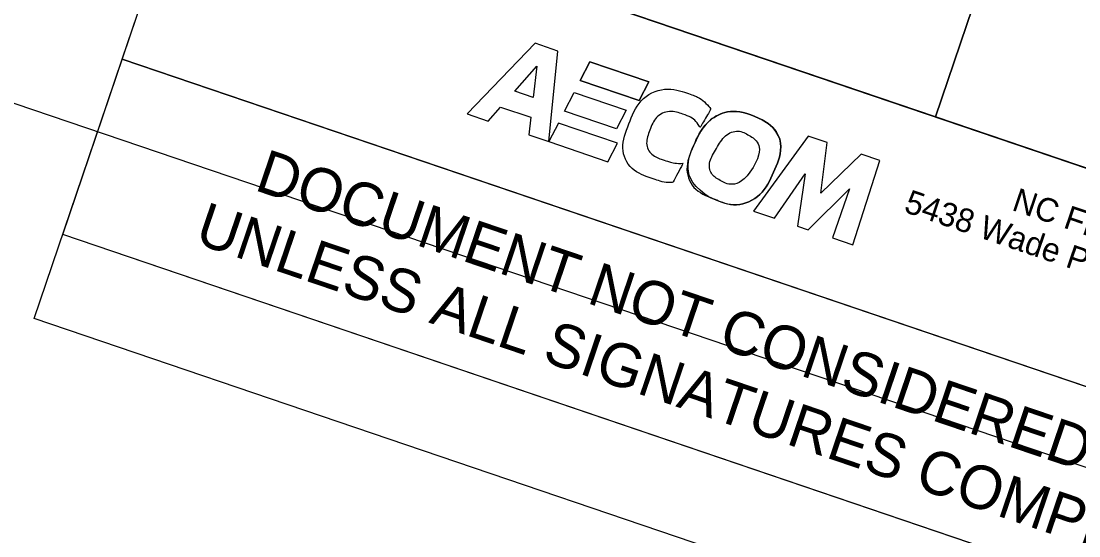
# Model space of a CAD drawing. Extents: x 2298691 to 2299860, y 598939 to 599889.
# Drawn here: x 2299689.8 to 2299770.4, y 599455.3 to 599494.4 of the extents above; entities that cross this region are included whole.
import ezdxf

# ---------------------------------------------------------------- set-up
doc = ezdxf.new("R2010")
doc.units = 0
for name, color, linetype in [('Default', 7, 'Continuous'), ('Prop DSN Text', 7, 'Continuous'), ('Scratch_Level_0', 7, 'Continuous'), ('Sheet Block Title CELL', 7, 'Continuous'), ('Sheet Border Standard 30in CELL', 7, 'Continuous'), ('Sheet Layout Plan Border', 7, 'Continuous'), ('Sheet Plan Layout CELL', 7, 'Continuous'), ('Sheet Sticker Exception Certification CELL', 7, 'Continuous')]:
    doc.layers.add(name, color=color, linetype=linetype)

# ---------------------------------------------------------------- blocks, each defined once
blk = doc.blocks.new('block 3')
at = {"layer": 'Default'}
blk.add_open_spline([(0.12275, 0.09393), (0.12554, 0.09373), (0.12726, 0.09146), (0.12695, 0.08843), (0.12663, 0.08531), (0.12411, 0.08298), (0.12127, 0.08318), (0.11848, 0.08338), (0.11676, 0.08565), (0.11707, 0.08868), (0.11739, 0.0918), (0.11991, 0.09413), (0.12275, 0.09393)], degree=3, dxfattribs=at)
blk = doc.blocks.new('block 2')
at = {"layer": 'Default'}
for p, q in [((0.10234, 0.09375), (0.10197, 0.09133)), ((0.10966, 0.09375), (0.10234, 0.09375)), ((0.10929, 0.09133), (0.10966, 0.09375)), ((0.10197, 0.09133), (0.10929, 0.09133)), ((0.10137, 0.08733), (0.10174, 0.08975)), ((0.10174, 0.08975), (0.10818, 0.08975)), ((0.10818, 0.08975), (0.10782, 0.08733)), ((0.10782, 0.08733), (0.10137, 0.08733)), ((0.10114, 0.08576), (0.10078, 0.08333)), ((0.10846, 0.08576), (0.10114, 0.08576)), ((0.1081, 0.08333), (0.10846, 0.08576)), ((0.10078, 0.08333), (0.1081, 0.08333))]:
    blk.add_line(p, q, dxfattribs=at)
for points in [[(0.10929, 0.09133), (0.10197, 0.09133), (0.10234, 0.09375), (0.10966, 0.09375), (0.10929, 0.09133)], [(0.10782, 0.08733), (0.10137, 0.08733), (0.10174, 0.08975), (0.10818, 0.08975), (0.10782, 0.08733)], [(0.10846, 0.08576), (0.10114, 0.08576), (0.10078, 0.08333), (0.1081, 0.08333), (0.10846, 0.08576)]]:
    blk.add_lwpolyline(points, dxfattribs=at)

msp = doc.modelspace()

# ---------------------------------------------------------------- linework, layer by layer
at = {"layer": 'Prop DSN Text'}
for p, q in [((2299728.973, 599492.752), (2299723.795, 599487.381)), ((2299730.704, 599492.163), (2299728.973, 599492.752)), ((2299730.01, 599485.271), (2299730.704, 599492.163)), ((2299727.415, 599489.112), (2299729.096, 599491.014)), ((2299729.11, 599491.009), (2299728.828, 599488.633)), ((2299729.096, 599491.014), (2299729.11, 599491.009)), ((2299728.828, 599488.633), (2299727.415, 599489.112)), ((2299723.795, 599487.381), (2299725.403, 599486.835)), ((2299725.403, 599486.835), (2299726.347, 599487.904)), ((2299726.347, 599487.904), (2299728.649, 599487.122)), ((2299728.649, 599487.122), (2299728.49, 599485.787)), ((2299728.49, 599485.787), (2299730.01, 599485.271)), ((2299749.754, 599485.694), (2299745.597, 599479.977)), ((2299751.193, 599485.205), (2299749.754, 599485.694)), ((2299750.713, 599481.347), (2299751.193, 599485.205)), ((2299753.783, 599484.326), (2299750.713, 599481.347)), ((2299755.224, 599483.836), (2299753.783, 599484.326)), ((2299753.17, 599477.405), (2299755.224, 599483.836)), ((2299747.185, 599479.437), (2299749.537, 599482.812)), ((2299749.537, 599482.812), (2299748.945, 599478.84)), ((2299749.755, 599478.565), (2299752.898, 599481.669)), ((2299752.898, 599481.669), (2299751.605, 599477.936)), ((2299745.597, 599479.977), (2299747.185, 599479.437)), ((2299748.945, 599478.84), (2299749.755, 599478.565)), ((2299751.605, 599477.936), (2299753.17, 599477.405))]:
    msp.add_line(p, q, dxfattribs=at)
for points in [[(2299728.49, 599485.787), (2299730.01, 599485.271), (2299730.704, 599492.163), (2299728.973, 599492.752), (2299723.795, 599487.381), (2299725.403, 599486.835), (2299726.347, 599487.904), (2299728.649, 599487.122), (2299728.49, 599485.787)], [(2299753.17, 599477.405), (2299755.224, 599483.836), (2299753.783, 599484.326), (2299750.713, 599481.347), (2299751.193, 599485.205), (2299749.754, 599485.694), (2299745.597, 599479.977), (2299747.185, 599479.437), (2299749.537, 599482.812), (2299748.945, 599478.84), (2299749.755, 599478.565), (2299752.898, 599481.669), (2299751.605, 599477.936), (2299753.17, 599477.405)]]:
    msp.add_lwpolyline(points, dxfattribs=at)
for points in [[(2299740.232, 599483.627), (2299739.736, 599483.574), (2299739.086, 599483.759), (2299738.772, 599483.866), (2299737.761, 599484.209), (2299737.325, 599485.126), (2299737.708, 599486.14), (2299738.112, 599487.211), (2299739.194, 599487.709), (2299740.305, 599487.332), (2299740.831, 599487.153), (2299741.234, 599486.823), (2299741.53, 599486.331), (2299741.53, 599486.331), (2299742.358, 599487.757), (2299742.358, 599487.757), (2299741.85, 599488.346), (2299741.369, 599488.68), (2299740.704, 599488.906), (2299738.864, 599489.531), (2299736.824, 599488.514), (2299736.106, 599486.609), (2299735.409, 599484.762), (2299736.178, 599483.037), (2299737.982, 599482.424), (2299738.295, 599482.317), (2299738.985, 599482.119), (2299739.48, 599482.172), (2299739.48, 599482.172), (2299740.232, 599483.627), (2299740.232, 599483.627)], [(2299740.232, 599483.627), (2299739.736, 599483.574), (2299739.086, 599483.759), (2299738.772, 599483.866), (2299737.761, 599484.209), (2299737.325, 599485.126), (2299737.708, 599486.14), (2299738.112, 599487.211), (2299739.194, 599487.709), (2299740.305, 599487.332), (2299740.831, 599487.153), (2299741.234, 599486.823), (2299741.53, 599486.331), (2299741.53, 599486.331), (2299742.358, 599487.757), (2299742.358, 599487.757), (2299741.85, 599488.346), (2299741.369, 599488.68), (2299740.704, 599488.906), (2299738.864, 599489.531), (2299736.824, 599488.514), (2299736.106, 599486.609), (2299735.409, 599484.762), (2299736.178, 599483.037), (2299737.982, 599482.424), (2299738.295, 599482.317), (2299738.985, 599482.119), (2299739.48, 599482.172), (2299739.48, 599482.172), (2299740.232, 599483.627), (2299740.232, 599483.627)], [(2299741.929, 599481.253), (2299740.75, 599482.091), (2299740.412, 599483.607), (2299741.122, 599485.156), (2299741.97, 599487.006), (2299744.001, 599487.908), (2299745.704, 599487.191)], [(2299745.704, 599487.191), (2299747.372, 599486.489), (2299747.957, 599484.738), (2299747.134, 599482.943), (2299746.286, 599481.093), (2299744.254, 599480.191), (2299742.552, 599480.908), (2299742.324, 599481.004), (2299742.116, 599481.12), (2299741.929, 599481.253)], [(2299745.561, 599483.304), (2299746.16, 599484.306), (2299746.044, 599485.284), (2299745.284, 599485.728), (2299744.448, 599486.217), (2299743.399, 599485.807), (2299742.765, 599484.749), (2299742.165, 599483.747), (2299742.281, 599482.769), (2299743.041, 599482.324), (2299743.877, 599481.836), (2299744.927, 599482.246), (2299745.561, 599483.304)], [(2299745.561, 599483.304), (2299746.16, 599484.306), (2299746.044, 599485.284), (2299745.284, 599485.728), (2299744.448, 599486.217), (2299743.399, 599485.807), (2299742.765, 599484.749), (2299742.165, 599483.747), (2299742.281, 599482.769), (2299743.041, 599482.324), (2299743.877, 599481.836), (2299744.927, 599482.246), (2299745.561, 599483.304)]]:
    msp.add_open_spline(points, degree=3, dxfattribs=at)
at = {"layer": 'Scratch_Level_0'}
msp.add_lwpolyline([(2299002.403, 599823.524), (2298809.463, 599255.407), (2299633.245, 598975.617), (2299795.103, 599452.239), (2299681.456, 599490.838), (2299712.532, 599582.335)], close=True, dxfattribs=at)
at = {"layer": 'Sheet Block Title CELL'}
msp.add_lwpolyline([(2299702.605, 599506.467), (2299816.231, 599467.875), (2299811.166, 599452.962), (2299697.54, 599491.554)], close=True, dxfattribs=at)
at = {"layer": 'Sheet Border Standard 30in CELL'}
for points in [[(2299724.313, 599570.381), (2299781.154, 599551.075), (2299759.446, 599487.161), (2299702.605, 599506.467)], [(2299781.154, 599551.075), (2299837.967, 599531.779), (2299816.259, 599467.865), (2299759.446, 599487.161)]]:
    msp.add_lwpolyline(points, close=True, dxfattribs=at)
at = {"layer": 'Sheet Layout Plan Border'}
msp.add_lwpolyline([(2299035.493, 599796.458), (2298855.433, 599254.004), (2299623.37, 598993.181), (2299776.096, 599442.853), (2299690.835, 599471.811), (2299700.483, 599500.217), (2299721.915, 599563.321), (2299035.493, 599796.458)], close=True, dxfattribs=at)
at = {"layer": 'Sheet Plan Layout CELL'}
msp.add_lwpolyline([(2298993.024, 599842.551), (2298790.436, 599246.028), (2299642.625, 598956.59), (2299806.65, 599439.597), (2299693.006, 599478.203), (2299731.559, 599591.714)], close=True, dxfattribs=at)
at = {"layer": 'Sheet Sticker Exception Certification CELL'}
for p, q in [((2299693.006, 599478.203), (2299697.54, 599491.554)), ((2299697.54, 599491.554), (2299811.187, 599452.955)), ((2299806.653, 599439.604), (2299693.006, 599478.203))]:
    msp.add_line(p, q, dxfattribs=at)

# ---------------------------------------------------------------- block references
at = {"layer": 'Prop DSN Text', "xscale": 648.0018668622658, "yscale": 648.0018668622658, "rotation": -18.759577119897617}
for name in ['block 2', 'block 3']:
    msp.add_blockref(name, (2299650.81, 599455.14), dxfattribs=at)

# ---------------------------------------------------------------- texts
at = {"layer": 'Prop DSN Text'}
for s, p in [('NC FIRM LICENSE No: F-0342', (2299765.183, 599480.077)), ('5438 Wade Park Boulevard, Suite 200', (2299756.972, 599479.943))]:
    msp.add_text(s, height=1.80001, rotation=341.24042, dxfattribs=at).set_placement(p)
at = {"layer": 'Sheet Sticker Exception Certification CELL'}
for s, p in [('DOCUMENT NOT CONSIDERED FINAL', (2299707.515, 599481.611)), ('UNLESS ALL SIGNATURES COMPLETED', (2299702.936, 599477.59))]:
    msp.add_text(s, height=3.30002, rotation=341.24042, dxfattribs=at).set_placement(p)

doc.saveas('drawing.dxf')
